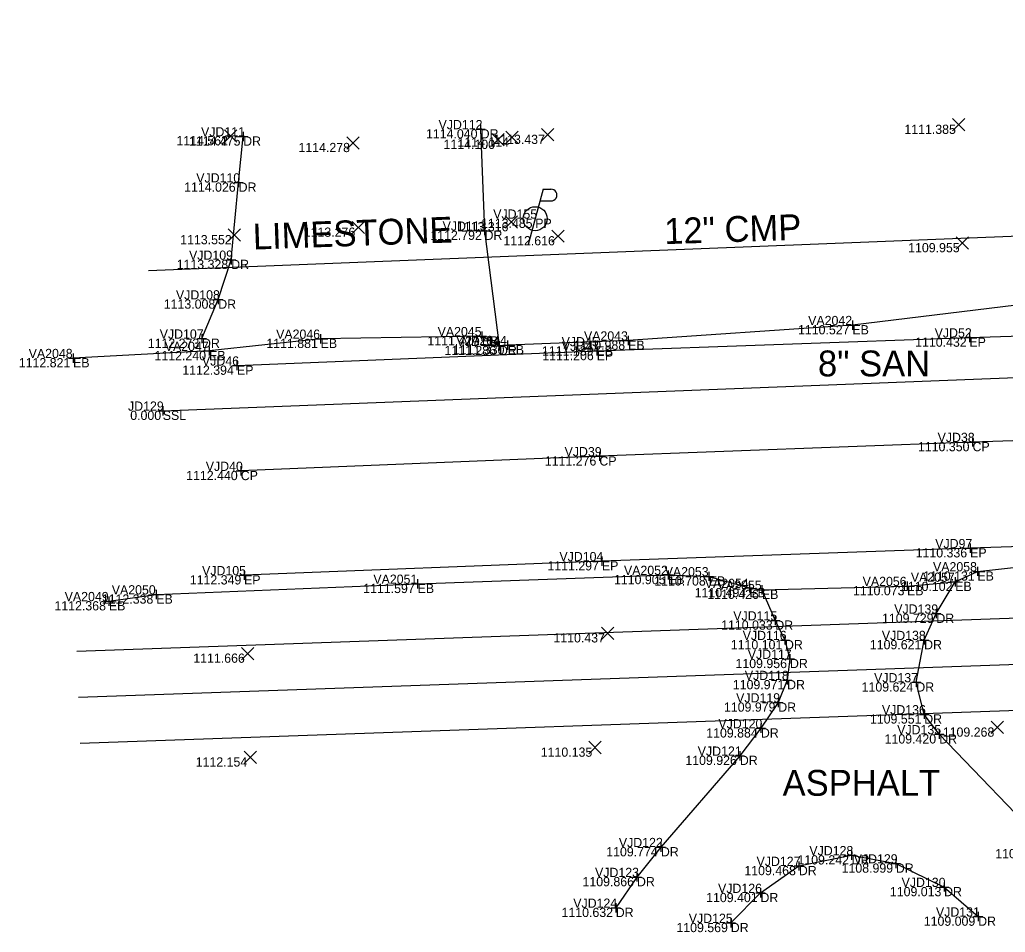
# Model space of a CAD drawing. Extents: x 1629915 to 1630675, y 484401 to 484601.
# Drawn here: x 1629915.3 to 1630022, y 484427.2 to 484526.1 of the extents above; entities that cross this region are included whole.
import ezdxf

# ---------------------------------------------------------------- set-up
doc = ezdxf.new("R2010")
doc.units = 0
for name, color, linetype in [('BR_X_Sub_Foot_Object', 7, 'Continuous'), ('DR_X_Storm_Sewer', 7, 'Continuous'), ('PV_X_COP', 7, 'Continuous'), ('PV_X_Driveway', 7, 'Continuous'), ('PV_X_EOP', 7, 'Continuous'), ('PV_X_Shoulder_Aggregate', 7, 'Continuous'), ('SV_X_Random_Point', 7, 'Continuous'), ('SV_X_Shot_Marker', 7, 'Continuous'), ('SV_X_Text_Comment', 7, 'Continuous'), ('SV_X_Text_Elevation', 7, 'Continuous'), ('SV_X_Text_Name', 7, 'Continuous'), ('TX_X_20', 7, 'Continuous'), ('UT_X_Electric_Cells', 7, 'Continuous'), ('UT_X_Sanitary_Line', 7, 'Continuous')]:
    doc.layers.add(name, color=color, linetype=linetype)

msp = doc.modelspace()

# ---------------------------------------------------------------- linework, layer by layer
at = {"layer": 'BR_X_Sub_Foot_Object'}
for p, q in [((1629921.46, 484457.7), (1630334.81, 484472.22)), ((1629921.64, 484452.7), (1630334.98, 484467.23)), ((1629921.81, 484447.71), (1630335.16, 484462.23))]:
    msp.add_line(p, q, dxfattribs=at)
at = {"layer": 'DR_X_Storm_Sewer'}
msp.add_line((1629929.22, 484498.91), (1630034.14, 484503.09), dxfattribs=at)
at = {"layer": 'PV_X_COP'}
msp.add_lwpolyline([(1630268.33, 484489.25), (1630243.24, 484488.19), (1630219.61, 484487.4), (1630181.89, 484485.93), (1630141.91, 484484.59), (1630101.85, 484483.16), (1630058.97, 484481.67), (1630018.45, 484480.34), (1629978.04, 484478.79), (1629939.2, 484477.21)], dxfattribs=at)
at = {"layer": 'PV_X_Driveway'}
for points in [[(1629935, 484491.54), (1629936.76, 484495.78), (1629938.16, 484500.08), (1629938.97, 484508.45), (1629939.46, 484513.44)], [(1629965.18, 484514.22), (1629965.6, 484503.23), (1629967.17, 484490.75)], [(1629995.64, 484464.34), (1629997.09, 484461.01), (1629998.14, 484458.89), (1629998.68, 484456.85), (1629998.37, 484454.56), (1629997.41, 484452.13), (1629995.53, 484449.33), (1629993.25, 484446.36), (1629984.7, 484436.46), (1629982.11, 484433.22), (1629979.81, 484429.89)], [(1630031.27, 484429.34), (1630029.07, 484432.86), (1630026.8, 484436.26), (1630014.84, 484448.68), (1630013.22, 484450.84), (1630012.36, 484454.31), (1630013.21, 484458.89), (1630014.53, 484461.75), (1630016.57, 484465.2)], [(1629992.27, 484428.25), (1629995.48, 484431.5), (1629999.64, 484434.42), (1630005.36, 484435.58), (1630010.15, 484434.69), (1630015.37, 484432.14), (1630019.06, 484428.94)]]:
    msp.add_lwpolyline(points, dxfattribs=at)
at = {"layer": 'PV_X_EOP'}
for points in [[(1629938.79, 484488.62), (1629977.75, 484490.2), (1630018.11, 484491.66), (1630058.6, 484492.97), (1630101.46, 484494.64), (1630141.53, 484496.09), (1630181.4, 484497.62), (1630219.2, 484499.13), (1630242.8, 484500), (1630272.75, 484501.05)], [(1630263.78, 484477.41), (1630243.53, 484476.68), (1630220, 484475.82), (1630182.22, 484474.5), (1630142.36, 484473.07), (1630102.12, 484471.6), (1630059.53, 484470.19), (1630018.19, 484468.84), (1629978.31, 484467.43), (1629939.56, 484465.91)]]:
    msp.add_lwpolyline(points, dxfattribs=at)
at = {"layer": 'PV_X_Shoulder_Aggregate'}
for points in [[(1630275.86, 484507.82), (1630275.94, 484508.43), (1630251.77, 484507.98), (1630226.06, 484507.18), (1630204.99, 484506.29), (1630180.18, 484504.73), (1630155.75, 484502.79), (1630130.5, 484501.38), (1630107.34, 484499.87), (1630082.61, 484498.88), (1630057.42, 484497.85), (1630056.68, 484498.18), (1630055.97, 484498.79), (1630036.74, 484497.12), (1630036.52, 484496.78), (1630005.44, 484493), (1629981.15, 484491.33), (1629968.09, 484490.84), (1629967.17, 484490.75), (1629965.31, 484491.8), (1629947.85, 484491.52), (1629935.77, 484490.2), (1629921.04, 484489.43)], [(1629924.92, 484463.1), (1629930.05, 484463.83), (1629958.35, 484464.98), (1629985.48, 484465.94), (1629989.88, 484465.79), (1629994.28, 484464.53), (1629995.64, 484464.34), (1630011.36, 484464.74), (1630016.57, 484465.2), (1630018.98, 484466.33), (1630028.74, 484467.4), (1630055.54, 484468.29), (1630066.15, 484468.61), (1630075.38, 484468), (1630095.19, 484466.53), (1630119.64, 484467.18), (1630148.03, 484467.95), (1630167.26, 484468.81), (1630191.18, 484469.68), (1630216.42, 484470.19), (1630228.43, 484470.02), (1630254.62, 484470.78), (1630261.49, 484471.01)]]:
    msp.add_lwpolyline(points, dxfattribs=at)
at = {"layer": 'SV_X_Random_Point'}
for p, q in [((1630016.27, 484514.05), (1630017.6, 484515.38)), ((1630016.27, 484515.38), (1630017.6, 484514.05)), ((1629937.44, 484512.81), (1629938.77, 484514.15)), ((1629937.44, 484514.15), (1629938.77, 484512.81)), ((1629950.68, 484512.07), (1629952.01, 484513.41)), ((1629950.68, 484513.41), (1629952.01, 484512.07)), ((1629966.4, 484512.41), (1629967.73, 484513.75)), ((1629966.4, 484513.75), (1629967.73, 484512.41)), ((1629967.92, 484512.66), (1629969.26, 484514)), ((1629967.92, 484514), (1629969.26, 484512.66)), ((1629971.78, 484512.96), (1629973.12, 484514.29)), ((1629971.78, 484514.29), (1629973.12, 484512.96)), ((1629967.84, 484503.49), (1629969.18, 484504.83)), ((1629967.84, 484504.83), (1629969.18, 484503.49)), ((1629951.26, 484502.91), (1629952.59, 484504.24)), ((1629951.26, 484504.24), (1629952.59, 484502.91)), ((1629937.84, 484502.1), (1629939.18, 484503.43)), ((1629937.84, 484503.43), (1629939.18, 484502.1)), ((1629972.88, 484501.97), (1629974.21, 484503.3)), ((1629972.88, 484503.3), (1629974.21, 484501.97)), ((1630016.68, 484501.22), (1630018.01, 484502.55)), ((1630016.68, 484502.55), (1630018.01, 484501.22)), ((1629978.28, 484458.96), (1629979.62, 484460.3)), ((1629978.28, 484460.3), (1629979.62, 484458.96)), ((1629939.29, 484456.76), (1629940.62, 484458.1)), ((1629939.29, 484458.1), (1629940.62, 484456.76)), ((1630020.46, 484448.75), (1630021.8, 484450.09)), ((1630020.46, 484450.09), (1630021.8, 484448.75)), ((1629976.89, 484446.58), (1629978.22, 484447.92)), ((1629976.89, 484447.92), (1629978.22, 484446.58)), ((1629939.57, 484445.52), (1629940.91, 484446.85)), ((1629939.57, 484446.85), (1629940.91, 484445.52))]:
    msp.add_line(p, q, dxfattribs=at)
at = {"layer": 'SV_X_Shot_Marker'}
for p, q in [((1629965.18, 484514.72), (1629965.18, 484513.72)), ((1629938.96, 484513.44), (1629939.96, 484513.44)), ((1629939.46, 484513.94), (1629939.46, 484512.94)), ((1629939.46, 484513.44), (1629939.46, 484513.44)), ((1629964.68, 484514.22), (1629965.68, 484514.22)), ((1629965.18, 484514.22), (1629965.18, 484514.22)), ((1629938.47, 484508.45), (1629939.47, 484508.45)), ((1629938.97, 484508.95), (1629938.97, 484507.95)), ((1629938.97, 484508.45), (1629938.97, 484508.45)), ((1629965.6, 484503.73), (1629965.6, 484502.73)), ((1629965.1, 484503.23), (1629966.1, 484503.23)), ((1629965.6, 484503.23), (1629965.6, 484503.23)), ((1629938.16, 484500.58), (1629938.16, 484499.58)), ((1629937.66, 484500.08), (1629938.66, 484500.08)), ((1629938.16, 484500.08), (1629938.16, 484500.08)), ((1629936.76, 484496.28), (1629936.76, 484495.28)), ((1629936.26, 484495.78), (1629937.26, 484495.78)), ((1629936.76, 484495.78), (1629936.76, 484495.78)), ((1630005.44, 484493.5), (1630005.44, 484492.5)), ((1629935, 484492.04), (1629935, 484491.04)), ((1629947.85, 484492.02), (1629947.85, 484491.02)), ((1629965.31, 484492.3), (1629965.31, 484491.3)), ((1630004.94, 484493), (1630005.94, 484493)), ((1630005.44, 484493), (1630005.44, 484493)), ((1630018.11, 484492.16), (1630018.11, 484491.16)), ((1629934.5, 484491.54), (1629935.5, 484491.54)), ((1629935, 484491.54), (1629935, 484491.54)), ((1629947.35, 484491.52), (1629948.35, 484491.52)), ((1629947.85, 484491.52), (1629947.85, 484491.52)), ((1629964.81, 484491.8), (1629965.81, 484491.8)), ((1629965.31, 484491.8), (1629965.31, 484491.8)), ((1629967.17, 484491.25), (1629967.17, 484490.25)), ((1629968.09, 484491.34), (1629968.09, 484490.34)), ((1629980.65, 484491.33), (1629981.65, 484491.33)), ((1629981.15, 484491.83), (1629981.15, 484490.83)), ((1629981.15, 484491.33), (1629981.15, 484491.33)), ((1630017.61, 484491.66), (1630018.61, 484491.66)), ((1630018.11, 484491.66), (1630018.11, 484491.66)), ((1629921.04, 484489.93), (1629921.04, 484488.93)), ((1629935.27, 484490.2), (1629936.27, 484490.2)), ((1629935.77, 484490.7), (1629935.77, 484489.7)), ((1629935.77, 484490.2), (1629935.77, 484490.2)), ((1629966.67, 484490.75), (1629967.67, 484490.75)), ((1629967.17, 484490.75), (1629967.17, 484490.75)), ((1629967.59, 484490.84), (1629968.59, 484490.84)), ((1629968.09, 484490.84), (1629968.09, 484490.84)), ((1629977.25, 484490.2), (1629978.25, 484490.2)), ((1629977.75, 484490.7), (1629977.75, 484489.7)), ((1629977.75, 484490.2), (1629977.75, 484490.2)), ((1629920.54, 484489.43), (1629921.54, 484489.43)), ((1629921.04, 484489.43), (1629921.04, 484489.43)), ((1629938.79, 484489.12), (1629938.79, 484488.12)), ((1629938.29, 484488.62), (1629939.29, 484488.62)), ((1629938.79, 484488.62), (1629938.79, 484488.62)), ((1629930.25, 484483.73), (1629931.25, 484483.73)), ((1629930.75, 484484.23), (1629930.75, 484483.23)), ((1629930.75, 484483.73), (1629930.75, 484483.73)), ((1630017.95, 484480.34), (1630018.95, 484480.34)), ((1630018.45, 484480.84), (1630018.45, 484479.84)), ((1630018.45, 484480.34), (1630018.45, 484480.34)), ((1629978.04, 484479.29), (1629978.04, 484478.29)), ((1629977.54, 484478.79), (1629978.54, 484478.79)), ((1629978.04, 484478.79), (1629978.04, 484478.79)), ((1629938.7, 484477.21), (1629939.7, 484477.21)), ((1629939.2, 484477.71), (1629939.2, 484476.71)), ((1629939.2, 484477.21), (1629939.2, 484477.21)), ((1630017.69, 484468.84), (1630018.69, 484468.84)), ((1630018.19, 484469.34), (1630018.19, 484468.34)), ((1630018.19, 484468.84), (1630018.19, 484468.84)), ((1629977.81, 484467.43), (1629978.81, 484467.43)), ((1629978.31, 484467.93), (1629978.31, 484466.93)), ((1629978.31, 484467.43), (1629978.31, 484467.43)), ((1629939.56, 484466.41), (1629939.56, 484465.41)), ((1629985.48, 484466.44), (1629985.48, 484465.44)), ((1630018.98, 484466.83), (1630018.98, 484465.83)), ((1629939.06, 484465.91), (1629940.06, 484465.91)), ((1629939.56, 484465.91), (1629939.56, 484465.91)), ((1629958.35, 484465.48), (1629958.35, 484464.48)), ((1629984.98, 484465.94), (1629985.98, 484465.94)), ((1629985.48, 484465.94), (1629985.48, 484465.94)), ((1629989.38, 484465.79), (1629990.38, 484465.79)), ((1629989.88, 484466.29), (1629989.88, 484465.29)), ((1629989.88, 484465.79), (1629989.88, 484465.79)), ((1630016.57, 484465.7), (1630016.57, 484464.7)), ((1630018.48, 484466.33), (1630019.48, 484466.33)), ((1630018.98, 484466.33), (1630018.98, 484466.33)), ((1629930.05, 484464.33), (1629930.05, 484463.33)), ((1629957.85, 484464.98), (1629958.85, 484464.98)), ((1629958.35, 484464.98), (1629958.35, 484464.98)), ((1629993.78, 484464.53), (1629994.78, 484464.53)), ((1629994.28, 484465.03), (1629994.28, 484464.03)), ((1629994.28, 484464.53), (1629994.28, 484464.53)), ((1629995.14, 484464.34), (1629996.14, 484464.34)), ((1629995.64, 484464.84), (1629995.64, 484463.84)), ((1629995.64, 484464.34), (1629995.64, 484464.34)), ((1630010.86, 484464.74), (1630011.86, 484464.74)), ((1630011.36, 484465.24), (1630011.36, 484464.24)), ((1630011.36, 484464.74), (1630011.36, 484464.74)), ((1630016.07, 484465.2), (1630017.07, 484465.2)), ((1630016.57, 484465.2), (1630016.57, 484465.2)), ((1629924.92, 484463.6), (1629924.92, 484462.6)), ((1629929.55, 484463.83), (1629930.55, 484463.83)), ((1629930.05, 484463.83), (1629930.05, 484463.83)), ((1629924.42, 484463.1), (1629925.42, 484463.1)), ((1629924.92, 484463.1), (1629924.92, 484463.1)), ((1630014.53, 484462.25), (1630014.53, 484461.25)), ((1629997.09, 484461.51), (1629997.09, 484460.51)), ((1630014.03, 484461.75), (1630015.03, 484461.75)), ((1630014.53, 484461.75), (1630014.53, 484461.75)), ((1629996.59, 484461.01), (1629997.59, 484461.01)), ((1629997.09, 484461.01), (1629997.09, 484461.01)), ((1629997.64, 484458.89), (1629998.64, 484458.89)), ((1629998.14, 484459.39), (1629998.14, 484458.39)), ((1629998.14, 484458.89), (1629998.14, 484458.89)), ((1630013.21, 484459.39), (1630013.21, 484458.39)), ((1630012.71, 484458.89), (1630013.71, 484458.89)), ((1630013.21, 484458.89), (1630013.21, 484458.89)), ((1629998.18, 484456.85), (1629999.18, 484456.85)), ((1629998.68, 484457.35), (1629998.68, 484456.35)), ((1629998.68, 484456.85), (1629998.68, 484456.85)), ((1629998.37, 484455.06), (1629998.37, 484454.06)), ((1630012.36, 484454.81), (1630012.36, 484453.81)), ((1629997.87, 484454.56), (1629998.87, 484454.56)), ((1629998.37, 484454.56), (1629998.37, 484454.56)), ((1630011.86, 484454.31), (1630012.86, 484454.31)), ((1630012.36, 484454.31), (1630012.36, 484454.31)), ((1629997.41, 484452.63), (1629997.41, 484451.63)), ((1629996.91, 484452.13), (1629997.91, 484452.13)), ((1629997.41, 484452.13), (1629997.41, 484452.13)), ((1630012.72, 484450.84), (1630013.72, 484450.84)), ((1630013.22, 484451.34), (1630013.22, 484450.34)), ((1630013.22, 484450.84), (1630013.22, 484450.84)), ((1629995.03, 484449.33), (1629996.03, 484449.33)), ((1629995.53, 484449.83), (1629995.53, 484448.83)), ((1629995.53, 484449.33), (1629995.53, 484449.33)), ((1630014.34, 484448.68), (1630015.34, 484448.68)), ((1630014.84, 484449.18), (1630014.84, 484448.18)), ((1630014.84, 484448.68), (1630014.84, 484448.68)), ((1629992.75, 484446.36), (1629993.75, 484446.36)), ((1629993.25, 484446.86), (1629993.25, 484445.86)), ((1629993.25, 484446.36), (1629993.25, 484446.36)), ((1629984.7, 484436.96), (1629984.7, 484435.96)), ((1629984.2, 484436.46), (1629985.2, 484436.46)), ((1629984.7, 484436.46), (1629984.7, 484436.46)), ((1630004.86, 484435.58), (1630005.86, 484435.58)), ((1630005.36, 484436.08), (1630005.36, 484435.08)), ((1630005.36, 484435.58), (1630005.36, 484435.58)), ((1629999.14, 484434.42), (1630000.14, 484434.42)), ((1629999.64, 484434.92), (1629999.64, 484433.92)), ((1629999.64, 484434.42), (1629999.64, 484434.42)), ((1630009.65, 484434.69), (1630010.65, 484434.69)), ((1630010.15, 484435.19), (1630010.15, 484434.19)), ((1630010.15, 484434.69), (1630010.15, 484434.69)), ((1629982.11, 484433.72), (1629982.11, 484432.72)), ((1629981.61, 484433.22), (1629982.61, 484433.22)), ((1629982.11, 484433.22), (1629982.11, 484433.22)), ((1630015.37, 484432.64), (1630015.37, 484431.64)), ((1629994.98, 484431.5), (1629995.98, 484431.5)), ((1629995.48, 484432), (1629995.48, 484431)), ((1629995.48, 484431.5), (1629995.48, 484431.5)), ((1630014.87, 484432.14), (1630015.87, 484432.14)), ((1630015.37, 484432.14), (1630015.37, 484432.14)), ((1629979.81, 484430.39), (1629979.81, 484429.39)), ((1629979.31, 484429.89), (1629980.31, 484429.89)), ((1629979.81, 484429.89), (1629979.81, 484429.89)), ((1630019.06, 484429.44), (1630019.06, 484428.44)), ((1629991.77, 484428.25), (1629992.77, 484428.25)), ((1629992.27, 484428.75), (1629992.27, 484427.75)), ((1629992.27, 484428.25), (1629992.27, 484428.25)), ((1630018.56, 484428.94), (1630019.56, 484428.94)), ((1630019.06, 484428.94), (1630019.06, 484428.94))]:
    msp.add_line(p, q, dxfattribs=at)
at = {"layer": 'UT_X_Electric_Cells'}
for p, q in [((1629971.95, 484507.73), (1629970.34, 484501.73)), ((1629971.95, 484507.73), (1629972.8, 484507.73)), ((1629971.61, 484506.45), (1629972.8, 484506.45))]:
    msp.add_line(p, q, dxfattribs=at)
msp.add_circle((1629971.09, 484504.53), 1.3, dxfattribs=at)
msp.add_arc((1629972.81, 484507.09), 0.638, 268.8767, 91.1233, dxfattribs=at)
at = {"layer": 'UT_X_Sanitary_Line'}
msp.add_lwpolyline([(1629930.75, 484483.73), (1630048.13, 484488.31), (1630252.72, 484494.6), (1630261.76, 484567.79), (1630373.42, 484500.09), (1630654.86, 484509.35)], dxfattribs=at)

# ---------------------------------------------------------------- texts
at = {"layer": 'SV_X_Text_Comment'}
for s, p in [('DR', (1629939.46, 484512.44)), ('DR', (1629965.18, 484513.22)), ('DR', (1629938.97, 484507.45)), ('PP', (1629971.09, 484503.53)), ('DR', (1629965.6, 484502.23)), ('DR', (1629938.16, 484499.08)), ('DR', (1629936.76, 484494.78)), ('EB', (1630005.44, 484492)), ('DR', (1629935, 484490.54)), ('EB', (1629947.85, 484490.52)), ('EB', (1629965.31, 484490.8)), ('EB', (1629981.15, 484490.33)), ('EP', (1630018.11, 484490.66)), ('EB', (1629935.77, 484489.2)), ('DR', (1629967.17, 484489.75)), ('EB', (1629968.09, 484489.84)), ('EB', (1629977.7, 484489.71)), ('EP', (1629977.75, 484489.2)), ('EB', (1629921.04, 484488.43)), ('EP', (1629938.79, 484487.62)), ('SSL', (1629930.75, 484482.73)), ('CP', (1630018.45, 484479.34)), ('CP', (1629978.04, 484477.79)), ('CP', (1629939.2, 484476.21)), ('EP', (1630018.19, 484467.84)), ('EP', (1629978.31, 484466.43)), ('EP', (1629939.56, 484464.91)), ('EB', (1629985.48, 484464.94)), ('EB', (1629989.88, 484464.79)), ('EB', (1630018.98, 484465.33)), ('EB', (1629958.35, 484463.98)), ('EB', (1629994.28, 484463.53)), ('EB', (1629995.64, 484463.34)), ('EB', (1630011.36, 484463.74)), ('EB', (1630016.57, 484464.2)), ('EB', (1629930.05, 484462.83)), ('EB', (1629924.92, 484462.1)), ('DR', (1630014.53, 484460.75)), ('DR', (1629997.09, 484460.01)), ('DR', (1629998.14, 484457.89)), ('DR', (1630013.21, 484457.89)), ('DR', (1629998.68, 484455.85)), ('DR', (1629998.37, 484453.56)), ('DR', (1630012.36, 484453.31)), ('DR', (1629997.41, 484451.13)), ('DR', (1630013.22, 484449.84)), ('DR', (1629995.53, 484448.33)), ('DR', (1630014.84, 484447.68)), ('DR', (1629993.25, 484445.36)), ('DR', (1629984.7, 484435.46)), ('DR', (1630005.36, 484434.58)), ('DR', (1629999.64, 484433.42)), ('DR', (1630010.15, 484433.69)), ('DR', (1629982.11, 484432.22)), ('DR', (1629995.48, 484430.5)), ('DR', (1630015.37, 484431.14)), ('DR', (1629979.81, 484428.89)), ('DR', (1629992.27, 484427.25)), ('DR', (1630019.06, 484427.94))]:
    msp.add_text(s, height=1, dxfattribs=at).set_placement(p)
at = {"layer": 'SV_X_Text_Elevation'}
for s, p in [('1111.385', (1630011.07, 484513.71)), ('1114.562', (1629932.23, 484512.48)), ('1114.475', (1629933.59, 484512.44)), ('1114.040', (1629959.26, 484513.22)), ('1114.114', (1629962.67, 484512.33)), ('1113.437', (1629966.56, 484512.62)), ('1114.278', (1629945.45, 484511.74)), ('1114.100', (1629961.16, 484512.08)), ('1114.026', (1629933.07, 484507.45)), ('1113.316', (1629962.61, 484503.16)), ('1113.485', (1629965.22, 484503.53)), ('1113.552', (1629932.64, 484501.76)), ('1113.276', (1629946.02, 484502.57)), ('1112.792', (1629959.73, 484502.23)), ('1112.616', (1629967.64, 484501.64)), ('1109.955', (1630011.48, 484500.89)), ('1113.328', (1629932.26, 484499.08)), ('1113.008', (1629930.86, 484494.78)), ('1110.527', (1629999.55, 484492)), ('1112.273', (1629929.13, 484490.54)), ('1111.881', (1629941.97, 484490.52)), ('1111.427', (1629959.41, 484490.8)), ('1110.988', (1629975.25, 484490.33)), ('1110.432', (1630012.24, 484490.66)), ('1112.240', (1629929.86, 484489.2)), ('1111.286', (1629961.26, 484489.75)), ('1111.330', (1629962.18, 484489.84)), ('1111.139', (1629971.82, 484489.71)), ('1111.206', (1629971.85, 484489.2)), ('1112.821', (1629915.16, 484488.43)), ('1112.394', (1629932.87, 484487.62)), ('0.000', (1629927.23, 484482.73)), ('1110.350', (1630012.54, 484479.34)), ('1111.276', (1629972.13, 484477.79)), ('1112.440', (1629933.29, 484476.21)), ('1110.336', (1630012.29, 484467.84)), ('1111.297', (1629972.41, 484466.43)), ('1112.349', (1629933.68, 484464.91)), ('1110.905', (1629979.62, 484464.94)), ('1110.708', (1629983.98, 484464.79)), ('1110.131', (1630013.11, 484465.33)), ('1111.597', (1629952.46, 484463.98)), ('1110.494', (1629988.36, 484463.53)), ('1110.426', (1629989.73, 484463.34)), ('1110.073', (1630005.5, 484463.74)), ('1110.102', (1630010.7, 484464.2)), ('1112.338', (1629924.15, 484462.83)), ('1112.368', (1629919.02, 484462.1)), ('1110.033', (1629991.23, 484460.01)), ('1109.729', (1630008.65, 484460.75)), ('1110.437', (1629973.06, 484458.63)), ('1110.101', (1629992.27, 484457.89)), ('1109.621', (1630007.33, 484457.89)), ('1111.666', (1629934.06, 484456.43)), ('1109.956', (1629992.78, 484455.85)), ('1109.971', (1629992.49, 484453.56)), ('1109.624', (1630006.44, 484453.31)), ('1109.979', (1629991.53, 484451.13)), ('1109.551', (1630007.34, 484449.84)), ('1109.884', (1629989.61, 484448.33)), ('1109.268', (1630015.23, 484448.42)), ('1109.420', (1630008.93, 484447.68)), ('1110.135', (1629971.69, 484446.25)), ('1112.154', (1629934.32, 484445.19)), ('1109.926', (1629987.35, 484445.36)), ('1109.774', (1629978.78, 484435.46)), ('1109.242', (1629999.49, 484434.58)), ('1108.619', (1630020.91, 484435.26)), ('1109.468', (1629993.74, 484433.42)), ('1108.999', (1630004.27, 484433.69)), ('1109.866', (1629976.21, 484432.22)), ('1109.401', (1629989.6, 484430.5)), ('1109.013', (1630009.5, 484431.14)), ('1110.632', (1629973.94, 484428.89)), ('1109.569', (1629986.38, 484427.25)), ('1109.009', (1630013.17, 484427.94))]:
    msp.add_text(s, height=1, dxfattribs=at).set_placement(p)
at = {"layer": 'SV_X_Text_Name'}
for s, p in [('VJD111', (1629934.9, 484513.44)), ('VJD112', (1629960.62, 484514.22)), ('VJD110', (1629934.38, 484508.45)), ('VJD155', (1629966.54, 484504.53)), ('VJD113', (1629961.06, 484503.23)), ('VJD109', (1629933.6, 484500.08)), ('VJD108', (1629932.18, 484495.78)), ('VA2042', (1630000.65, 484493)), ('VJD107', (1629930.42, 484491.54)), ('VA2046', (1629943.03, 484491.52)), ('VA2045', (1629960.52, 484491.8)), ('VA2043', (1629976.37, 484491.33)), ('VJD52', (1630014.35, 484491.66)), ('VA2047', (1629930.97, 484490.2)), ('VJD114', (1629962.56, 484490.75)), ('VA2044', (1629963.26, 484490.84)), ('VJD45', (1629973.95, 484490.71)), ('VJD47', (1629973.98, 484490.2)), ('VA2048', (1629916.23, 484489.43)), ('VJD46', (1629935, 484488.62)), ('JD129', (1629926.99, 484483.73)), ('VJD38', (1630014.67, 484480.34)), ('VJD39', (1629974.27, 484478.79)), ('VJD40', (1629935.41, 484477.21)), ('VJD97', (1630014.41, 484468.84)), ('VJD104', (1629973.71, 484467.43)), ('VJD105', (1629935.01, 484465.91)), ('VA2052', (1629980.7, 484465.94)), ('VA2053', (1629985.11, 484465.79)), ('VA2058', (1630014.17, 484466.33)), ('VA2051', (1629953.56, 484464.98)), ('VA2054', (1629989.45, 484464.53)), ('VA2055', (1629990.85, 484464.34)), ('VA2056', (1630006.55, 484464.74)), ('VA2057', (1630011.77, 484465.2)), ('VA2050', (1629925.23, 484463.83)), ('VA2049', (1629920.13, 484463.1)), ('VJD139', (1630009.97, 484461.75)), ('VJD115', (1629992.54, 484461.01)), ('VJD116', (1629993.56, 484458.89)), ('VJD138', (1630008.63, 484458.89)), ('VJD117', (1629994.11, 484456.85)), ('VJD118', (1629993.79, 484454.56)), ('VJD137', (1630007.79, 484454.31)), ('VJD119', (1629992.85, 484452.13)), ('VJD136', (1630008.64, 484450.84)), ('VJD120', (1629990.93, 484449.33)), ('VJD135', (1630010.29, 484448.68)), ('VJD121', (1629988.69, 484446.36)), ('VJD122', (1629980.15, 484436.46)), ('VJD128', (1630000.78, 484435.58)), ('VJD127', (1629995.06, 484434.42)), ('VJD129', (1630005.58, 484434.69)), ('VJD123', (1629977.57, 484433.22)), ('VJD126', (1629990.89, 484431.5)), ('VJD130', (1630010.77, 484432.14)), ('VJD124', (1629975.21, 484429.89)), ('VJD125', (1629987.72, 484428.25)), ('VJD131', (1630014.49, 484428.94))]:
    msp.add_text(s, height=1, dxfattribs=at).set_placement(p)
at = {"layer": 'TX_X_20'}
for s, rotation, p in [('12" CMP', 1.7995, (1629985.1, 484501.77)), ('LIMESTONE', 2.0563, (1629940.55, 484501.18)), ('ASPHALT', 360, (1629997.88, 484442.02))]:
    msp.add_text(s, height=2.8, rotation=rotation, dxfattribs=at).set_placement(p)
msp.add_text('8" SAN', height=2.8, dxfattribs=at).set_placement((1630001.71, 484487.45))

doc.saveas('drawing.dxf')
